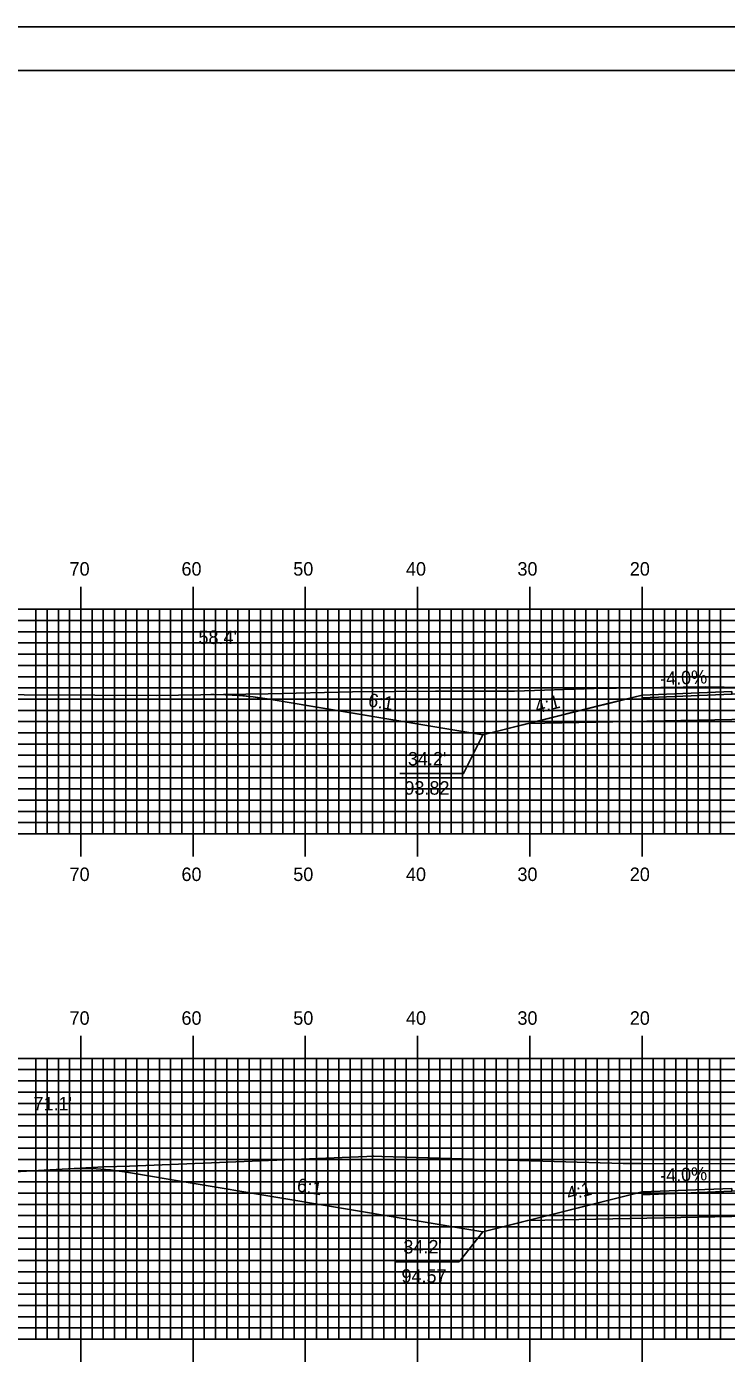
# Model space of a CAD drawing. Extents: x 1775170 to 1775514, y 442591 to 442811.
# Drawn here: x 1775261.4 to 1775323.7, y 442691.2 to 442810.5 of the extents above; entities that cross this region are included whole.
import ezdxf

# ---------------------------------------------------------------- set-up
doc = ezdxf.new("R2010")
doc.units = 0
for name, color, linetype in [('ANNOTATION', 7, 'Continuous'), ('BORDER', 7, 'Continuous'), ('D_Roadway_Centerline', 7, 'Continuous'), ('D_Roadway_Edge_Shoulder', 7, 'Continuous'), ('D_Roadway_SlopeLines', 7, 'Continuous'), ('D_Roadway_SubGrade', 7, 'Continuous'), ('D_Text_Standard', 7, 'Continuous'), ('H_V ANNOTATION', 7, 'Continuous'), ('MAJOR', 7, 'Continuous'), ('MINOR', 7, 'Continuous'), ('PLOT BOUNDARY', 7, 'Continuous'), ('S_Roadway_Centerline', 7, 'Continuous')]:
    doc.layers.add(name, color=color, linetype=linetype)

msp = doc.modelspace()

# ---------------------------------------------------------------- linework, layer by layer
at = {"layer": 'ANNOTATION'}
for points in [[(1775294.61, 442744.04), (1775300.3, 442744.04), (1775302.02, 442747.49)], [(1775294.21, 442700.57), (1775299.9, 442700.57), (1775302.02, 442703.24)]]:
    msp.add_lwpolyline(points, dxfattribs=at)
at = {"layer": 'BORDER'}
msp.add_lwpolyline([(1775186.6, 442596.67), (1775506.6, 442596.67), (1775506.6, 442806.67), (1775186.6, 442806.67)], close=True, dxfattribs=at)
at = {"layer": 'D_Roadway_Centerline'}
for points in [[(1775277.8, 442751.07), (1775278.06, 442751.07), (1775279.05, 442751.06), (1775280.3, 442751), (1775280.52, 442750.98), (1775281.55, 442750.87), (1775282.24, 442750.77), (1775282.8, 442750.7), (1775289.02, 442749.66), (1775302.02, 442747.49), (1775302.02, 442747.49), (1775306.02, 442748.49), (1775312.77, 442750.18), (1775316.2, 442751.03), (1775324.2, 442751.35)], [(1775265.08, 442708.84), (1775265.77, 442708.86), (1775266.33, 442708.87), (1775266.71, 442708.86), (1775267.58, 442708.84), (1775268.83, 442708.74), (1775268.87, 442708.73), (1775270.08, 442708.56), (1775302.02, 442703.24), (1775302.02, 442703.24), (1775306.02, 442704.24), (1775313.13, 442706.02), (1775316.2, 442706.78), (1775324.2, 442707.1)]]:
    msp.add_lwpolyline(points, dxfattribs=at)
at = {"layer": 'D_Roadway_Edge_Shoulder'}
for points in [[(1775324.2, 442751.35), (1775316.2, 442751.03), (1775316.2, 442750.78), (1775324.2, 442751.1)], [(1775324.2, 442707.1), (1775316.2, 442706.78), (1775316.2, 442706.53), (1775324.2, 442706.85)]]:
    msp.add_lwpolyline(points, close=True, dxfattribs=at)
at = {"layer": 'D_Roadway_SlopeLines'}
for points in [[(1775302.02, 442747.49), (1775282.8, 442750.7), (1775281.55, 442750.87), (1775280.3, 442751), (1775279.05, 442751.06), (1775277.8, 442751.07)], [(1775316.2, 442751.03), (1775302.02, 442747.49)], [(1775302.02, 442703.24), (1775270.08, 442708.56), (1775268.83, 442708.74), (1775267.58, 442708.84), (1775266.33, 442708.87), (1775265.08, 442708.84)], [(1775316.2, 442706.78), (1775302.02, 442703.24)]]:
    msp.add_lwpolyline(points, dxfattribs=at)
at = {"layer": 'D_Roadway_SubGrade'}
for points in [[(1775324.2, 442748.85), (1775306.02, 442748.49), (1775316.2, 442751.03), (1775316.2, 442750.78), (1775324.2, 442751.1), (1775336.2, 442751.34), (1775348.2, 442751.1), (1775356.2, 442750.78), (1775356.2, 442751.03), (1775366.37, 442748.49), (1775348.2, 442748.85), (1775336.2, 442749.09)], [(1775324.2, 442704.6), (1775306.02, 442704.24), (1775316.2, 442706.78), (1775316.2, 442706.53), (1775324.2, 442706.85), (1775336.2, 442707.09), (1775348.2, 442706.85), (1775356.2, 442706.53), (1775356.2, 442706.78), (1775366.37, 442704.24), (1775348.2, 442704.6), (1775336.2, 442704.84)]]:
    msp.add_lwpolyline(points, close=True, dxfattribs=at)
at = {"layer": 'MAJOR'}
for p, q in [((1775266.2, 442760.67), (1775266.2, 442758.67)), ((1775276.2, 442760.67), (1775276.2, 442758.67)), ((1775286.2, 442760.67), (1775286.2, 442758.67)), ((1775296.2, 442760.67), (1775296.2, 442758.67)), ((1775306.2, 442760.67), (1775306.2, 442758.67)), ((1775316.2, 442760.67), (1775316.2, 442758.67)), ((1775196.2, 442758.67), (1775476.2, 442758.67)), ((1775196.2, 442758.67), (1775476.2, 442758.67)), ((1775266.2, 442738.67), (1775266.2, 442758.67)), ((1775276.2, 442738.67), (1775276.2, 442758.67)), ((1775286.2, 442738.67), (1775286.2, 442758.67)), ((1775296.2, 442738.67), (1775296.2, 442758.67)), ((1775306.2, 442738.67), (1775306.2, 442758.67)), ((1775316.2, 442738.67), (1775316.2, 442758.67)), ((1775196.2, 442753.67), (1775476.2, 442753.67)), ((1775196.2, 442748.67), (1775476.2, 442748.67)), ((1775196.2, 442743.67), (1775476.2, 442743.67)), ((1775196.2, 442738.67), (1775476.2, 442738.67)), ((1775196.2, 442738.67), (1775476.2, 442738.67)), ((1775266.2, 442736.66), (1775266.2, 442738.67)), ((1775276.2, 442736.66), (1775276.2, 442738.67)), ((1775286.2, 442736.66), (1775286.2, 442738.67)), ((1775296.2, 442736.66), (1775296.2, 442738.67)), ((1775306.2, 442736.66), (1775306.2, 442738.67)), ((1775316.2, 442736.66), (1775316.2, 442738.67)), ((1775266.2, 442720.67), (1775266.2, 442718.67)), ((1775276.2, 442720.67), (1775276.2, 442718.67)), ((1775286.2, 442720.67), (1775286.2, 442718.67)), ((1775296.2, 442720.67), (1775296.2, 442718.67)), ((1775306.2, 442720.67), (1775306.2, 442718.67)), ((1775316.2, 442720.67), (1775316.2, 442718.67)), ((1775196.2, 442718.67), (1775476.2, 442718.67)), ((1775196.2, 442718.67), (1775476.2, 442718.67)), ((1775266.2, 442693.67), (1775266.2, 442718.67)), ((1775276.2, 442693.67), (1775276.2, 442718.67)), ((1775286.2, 442693.67), (1775286.2, 442718.67)), ((1775296.2, 442693.67), (1775296.2, 442718.67)), ((1775306.2, 442693.67), (1775306.2, 442718.67)), ((1775316.2, 442693.67), (1775316.2, 442718.67)), ((1775196.2, 442713.67), (1775476.2, 442713.67)), ((1775196.2, 442708.67), (1775476.2, 442708.67)), ((1775196.2, 442703.67), (1775476.2, 442703.67)), ((1775196.2, 442698.67), (1775476.2, 442698.67)), ((1775196.2, 442693.67), (1775476.2, 442693.67)), ((1775196.2, 442693.67), (1775476.2, 442693.67)), ((1775266.2, 442691.66), (1775266.2, 442693.67)), ((1775276.2, 442691.66), (1775276.2, 442693.67)), ((1775286.2, 442691.66), (1775286.2, 442693.67)), ((1775296.2, 442691.66), (1775296.2, 442693.67)), ((1775306.2, 442691.66), (1775306.2, 442693.67)), ((1775316.2, 442691.66), (1775316.2, 442693.67))]:
    msp.add_line(p, q, dxfattribs=at)
at = {"layer": 'MINOR'}
for p, q in [((1775262.2, 442738.67), (1775262.2, 442758.67)), ((1775263.2, 442738.67), (1775263.2, 442758.67)), ((1775264.2, 442738.67), (1775264.2, 442758.67)), ((1775265.2, 442738.67), (1775265.2, 442758.67)), ((1775267.2, 442738.67), (1775267.2, 442758.67)), ((1775268.2, 442738.67), (1775268.2, 442758.67)), ((1775269.2, 442738.67), (1775269.2, 442758.67)), ((1775270.2, 442738.67), (1775270.2, 442758.67)), ((1775271.2, 442738.67), (1775271.2, 442758.67)), ((1775272.2, 442738.67), (1775272.2, 442758.67)), ((1775273.2, 442738.67), (1775273.2, 442758.67)), ((1775274.2, 442738.67), (1775274.2, 442758.67)), ((1775275.2, 442738.67), (1775275.2, 442758.67)), ((1775277.2, 442738.67), (1775277.2, 442758.67)), ((1775278.2, 442738.67), (1775278.2, 442758.67)), ((1775279.2, 442738.67), (1775279.2, 442758.67)), ((1775280.2, 442738.67), (1775280.2, 442758.67)), ((1775281.2, 442738.67), (1775281.2, 442758.67)), ((1775282.2, 442738.67), (1775282.2, 442758.67)), ((1775283.2, 442738.67), (1775283.2, 442758.67)), ((1775284.2, 442738.67), (1775284.2, 442758.67)), ((1775285.2, 442738.67), (1775285.2, 442758.67)), ((1775287.2, 442738.67), (1775287.2, 442758.67)), ((1775288.2, 442738.67), (1775288.2, 442758.67)), ((1775289.2, 442738.67), (1775289.2, 442758.67)), ((1775290.2, 442738.67), (1775290.2, 442758.67)), ((1775291.2, 442738.67), (1775291.2, 442758.67)), ((1775292.2, 442738.67), (1775292.2, 442758.67)), ((1775293.2, 442738.67), (1775293.2, 442758.67)), ((1775294.2, 442738.67), (1775294.2, 442758.67)), ((1775295.2, 442738.67), (1775295.2, 442758.67)), ((1775297.2, 442738.67), (1775297.2, 442758.67)), ((1775298.2, 442738.67), (1775298.2, 442758.67)), ((1775299.2, 442738.67), (1775299.2, 442758.67)), ((1775300.2, 442738.67), (1775300.2, 442758.67)), ((1775301.2, 442738.67), (1775301.2, 442758.67)), ((1775302.2, 442738.67), (1775302.2, 442758.67)), ((1775303.2, 442738.67), (1775303.2, 442758.67)), ((1775304.2, 442738.67), (1775304.2, 442758.67)), ((1775305.2, 442738.67), (1775305.2, 442758.67)), ((1775307.2, 442738.67), (1775307.2, 442758.67)), ((1775308.2, 442738.67), (1775308.2, 442758.67)), ((1775309.2, 442738.67), (1775309.2, 442758.67)), ((1775310.2, 442738.67), (1775310.2, 442758.67)), ((1775311.2, 442738.67), (1775311.2, 442758.67)), ((1775312.2, 442738.67), (1775312.2, 442758.67)), ((1775313.2, 442738.67), (1775313.2, 442758.67)), ((1775314.2, 442738.67), (1775314.2, 442758.67)), ((1775315.2, 442738.67), (1775315.2, 442758.67)), ((1775317.2, 442738.67), (1775317.2, 442758.67)), ((1775318.2, 442738.67), (1775318.2, 442758.67)), ((1775319.2, 442738.67), (1775319.2, 442758.67)), ((1775320.2, 442738.67), (1775320.2, 442758.67)), ((1775321.2, 442738.67), (1775321.2, 442758.67)), ((1775322.2, 442738.67), (1775322.2, 442758.67)), ((1775323.2, 442738.67), (1775323.2, 442758.67)), ((1775196.2, 442757.67), (1775476.2, 442757.67)), ((1775196.2, 442756.67), (1775476.2, 442756.67)), ((1775196.2, 442755.67), (1775476.2, 442755.67)), ((1775196.2, 442754.67), (1775476.2, 442754.67)), ((1775196.2, 442752.67), (1775476.2, 442752.67)), ((1775196.2, 442751.67), (1775476.2, 442751.67)), ((1775196.2, 442750.67), (1775476.2, 442750.67)), ((1775196.2, 442749.67), (1775476.2, 442749.67)), ((1775196.2, 442747.67), (1775476.2, 442747.67)), ((1775196.2, 442746.67), (1775476.2, 442746.67)), ((1775196.2, 442745.67), (1775476.2, 442745.67)), ((1775196.2, 442744.67), (1775476.2, 442744.67)), ((1775196.2, 442742.67), (1775476.2, 442742.67)), ((1775196.2, 442741.67), (1775476.2, 442741.67)), ((1775196.2, 442740.67), (1775476.2, 442740.67)), ((1775196.2, 442739.67), (1775476.2, 442739.67)), ((1775262.2, 442693.67), (1775262.2, 442718.67)), ((1775263.2, 442693.67), (1775263.2, 442718.67)), ((1775264.2, 442693.67), (1775264.2, 442718.67)), ((1775265.2, 442693.67), (1775265.2, 442718.67)), ((1775267.2, 442693.67), (1775267.2, 442718.67)), ((1775268.2, 442693.67), (1775268.2, 442718.67)), ((1775269.2, 442693.67), (1775269.2, 442718.67)), ((1775270.2, 442693.67), (1775270.2, 442718.67)), ((1775271.2, 442693.67), (1775271.2, 442718.67)), ((1775272.2, 442693.67), (1775272.2, 442718.67)), ((1775273.2, 442693.67), (1775273.2, 442718.67)), ((1775274.2, 442693.67), (1775274.2, 442718.67)), ((1775275.2, 442693.67), (1775275.2, 442718.67)), ((1775277.2, 442693.67), (1775277.2, 442718.67)), ((1775278.2, 442693.67), (1775278.2, 442718.67)), ((1775279.2, 442693.67), (1775279.2, 442718.67)), ((1775280.2, 442693.67), (1775280.2, 442718.67)), ((1775281.2, 442693.67), (1775281.2, 442718.67)), ((1775282.2, 442693.67), (1775282.2, 442718.67)), ((1775283.2, 442693.67), (1775283.2, 442718.67)), ((1775284.2, 442693.67), (1775284.2, 442718.67)), ((1775285.2, 442693.67), (1775285.2, 442718.67)), ((1775287.2, 442693.67), (1775287.2, 442718.67)), ((1775288.2, 442693.67), (1775288.2, 442718.67)), ((1775289.2, 442693.67), (1775289.2, 442718.67)), ((1775290.2, 442693.67), (1775290.2, 442718.67)), ((1775291.2, 442693.67), (1775291.2, 442718.67)), ((1775292.2, 442693.67), (1775292.2, 442718.67)), ((1775293.2, 442693.67), (1775293.2, 442718.67)), ((1775294.2, 442693.67), (1775294.2, 442718.67)), ((1775295.2, 442693.67), (1775295.2, 442718.67)), ((1775297.2, 442693.67), (1775297.2, 442718.67)), ((1775298.2, 442693.67), (1775298.2, 442718.67)), ((1775299.2, 442693.67), (1775299.2, 442718.67)), ((1775300.2, 442693.67), (1775300.2, 442718.67)), ((1775301.2, 442693.67), (1775301.2, 442718.67)), ((1775302.2, 442693.67), (1775302.2, 442718.67)), ((1775303.2, 442693.67), (1775303.2, 442718.67)), ((1775304.2, 442693.67), (1775304.2, 442718.67)), ((1775305.2, 442693.67), (1775305.2, 442718.67)), ((1775307.2, 442693.67), (1775307.2, 442718.67)), ((1775308.2, 442693.67), (1775308.2, 442718.67)), ((1775309.2, 442693.67), (1775309.2, 442718.67)), ((1775310.2, 442693.67), (1775310.2, 442718.67)), ((1775311.2, 442693.67), (1775311.2, 442718.67)), ((1775312.2, 442693.67), (1775312.2, 442718.67)), ((1775313.2, 442693.67), (1775313.2, 442718.67)), ((1775314.2, 442693.67), (1775314.2, 442718.67)), ((1775315.2, 442693.67), (1775315.2, 442718.67)), ((1775317.2, 442693.67), (1775317.2, 442718.67)), ((1775318.2, 442693.67), (1775318.2, 442718.67)), ((1775319.2, 442693.67), (1775319.2, 442718.67)), ((1775320.2, 442693.67), (1775320.2, 442718.67)), ((1775321.2, 442693.67), (1775321.2, 442718.67)), ((1775322.2, 442693.67), (1775322.2, 442718.67)), ((1775323.2, 442693.67), (1775323.2, 442718.67)), ((1775196.2, 442717.67), (1775476.2, 442717.67)), ((1775196.2, 442716.67), (1775476.2, 442716.67)), ((1775196.2, 442715.67), (1775476.2, 442715.67)), ((1775196.2, 442714.67), (1775476.2, 442714.67)), ((1775196.2, 442712.67), (1775476.2, 442712.67)), ((1775196.2, 442711.67), (1775476.2, 442711.67)), ((1775196.2, 442710.67), (1775476.2, 442710.67)), ((1775196.2, 442709.67), (1775476.2, 442709.67)), ((1775196.2, 442707.67), (1775476.2, 442707.67)), ((1775196.2, 442706.67), (1775476.2, 442706.67)), ((1775196.2, 442705.67), (1775476.2, 442705.67)), ((1775196.2, 442704.67), (1775476.2, 442704.67)), ((1775196.2, 442702.67), (1775476.2, 442702.67)), ((1775196.2, 442701.67), (1775476.2, 442701.67)), ((1775196.2, 442700.67), (1775476.2, 442700.67)), ((1775196.2, 442699.67), (1775476.2, 442699.67)), ((1775196.2, 442697.67), (1775476.2, 442697.67)), ((1775196.2, 442696.67), (1775476.2, 442696.67)), ((1775196.2, 442695.67), (1775476.2, 442695.67)), ((1775196.2, 442694.67), (1775476.2, 442694.67))]:
    msp.add_line(p, q, dxfattribs=at)
at = {"layer": 'PLOT BOUNDARY'}
msp.add_lwpolyline([(1775170.41, 442590.55), (1775510.41, 442590.55), (1775510.41, 442810.55), (1775170.41, 442810.55)], close=True, dxfattribs=at)
at = {"layer": 'S_Roadway_Centerline'}
for points in [[(1775248.52, 442751.12), (1775267.46, 442751.03), (1775272.93, 442751), (1775282.9, 442751.15), (1775290.4, 442751.31), (1775297.79, 442751.39), (1775304.85, 442751.38), (1775311.93, 442751.61), (1775321.84, 442751.77), (1775328.56, 442751.66), (1775335.27, 442751.62), (1775344.39, 442751.79), (1775351.81, 442752.02), (1775358.68, 442751.94), (1775368.26, 442752), (1775374.79, 442751.93), (1775381.79, 442751.94), (1775387.46, 442751.79), (1775392.41, 442751.75), (1775403.92, 442751.56)], [(1775257.1, 442708.39), (1775268.25, 442709.02), (1775270.54, 442709.07), (1775291.68, 442709.94), (1775292.24, 442709.97), (1775292.27, 442709.97), (1775292.3, 442709.96), (1775293.03, 442709.95), (1775314.53, 442709.3), (1775316.13, 442709.31), (1775328.06, 442709.29), (1775338.2, 442708.9), (1775340.24, 442708.8), (1775360.74, 442708.31), (1775362.47, 442708.3), (1775364.22, 442708.29), (1775374.57, 442708.26), (1775382.75, 442707.71), (1775385.58, 442707.67), (1775407.68, 442707.44)]]:
    msp.add_lwpolyline(points, dxfattribs=at)

# ---------------------------------------------------------------- texts
at = {"layer": 'ANNOTATION'}
for s, rotation, p in [('-4.0%', 2.2909, (1775317.83, 442751.9)), ('6:1', 350.5363, (1775291.74, 442750.03)), ('4:1', 14.0382, (1775306.83, 442749.38)), ('-4.0%', 2.2905, (1775317.83, 442707.65)), ('6:1', 350.5383, (1775285.39, 442706.84)), ('4:1', 14.0391, (1775309.65, 442706.01))]:
    msp.add_text(s, height=1.2, rotation=rotation, dxfattribs=at).set_placement(p)
for s, p in [("34.2'", (1775295.34, 442744.76)), ('93.82', (1775295.03, 442742.16)), ("34.2'", (1775294.94, 442701.3)), ('94.57', (1775294.77, 442698.7))]:
    msp.add_text(s, height=1.2, dxfattribs=at).set_placement(p)
at = {"layer": 'D_Text_Standard'}
for s, p in [("58.4'", (1775276.68, 442755.58)), ("71.1'", (1775261.99, 442714.05))]:
    msp.add_text(s, height=1.2, dxfattribs=at).set_placement(p)
at = {"layer": 'H_V ANNOTATION'}
for s, p in [('70', (1775265.2, 442761.67)), ('60', (1775275.17, 442761.67)), ('50', (1775285.13, 442761.67)), ('40', (1775295.17, 442761.67)), ('30', (1775305.1, 442761.67)), ('20', (1775315.11, 442761.67)), ('70', (1775265.2, 442734.47)), ('60', (1775275.17, 442734.47)), ('50', (1775285.13, 442734.47)), ('40', (1775295.17, 442734.47)), ('30', (1775305.1, 442734.47)), ('20', (1775315.11, 442734.47)), ('70', (1775265.2, 442721.67)), ('60', (1775275.17, 442721.67)), ('50', (1775285.13, 442721.67)), ('40', (1775295.17, 442721.67)), ('30', (1775305.1, 442721.67)), ('20', (1775315.11, 442721.67))]:
    msp.add_text(s, height=1.2, dxfattribs=at).set_placement(p)

doc.saveas('drawing.dxf')
